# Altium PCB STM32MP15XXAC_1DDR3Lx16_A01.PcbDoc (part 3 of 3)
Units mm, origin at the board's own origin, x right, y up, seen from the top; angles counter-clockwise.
Board outline 89 x 120 mm, 4 copper layers (Top Layer, Signal Layer 1, Signal Layer 2, Bottom Layer), stack 1.571 mm thick; 133 components, 92 nets, 915 pads, 400 vias.
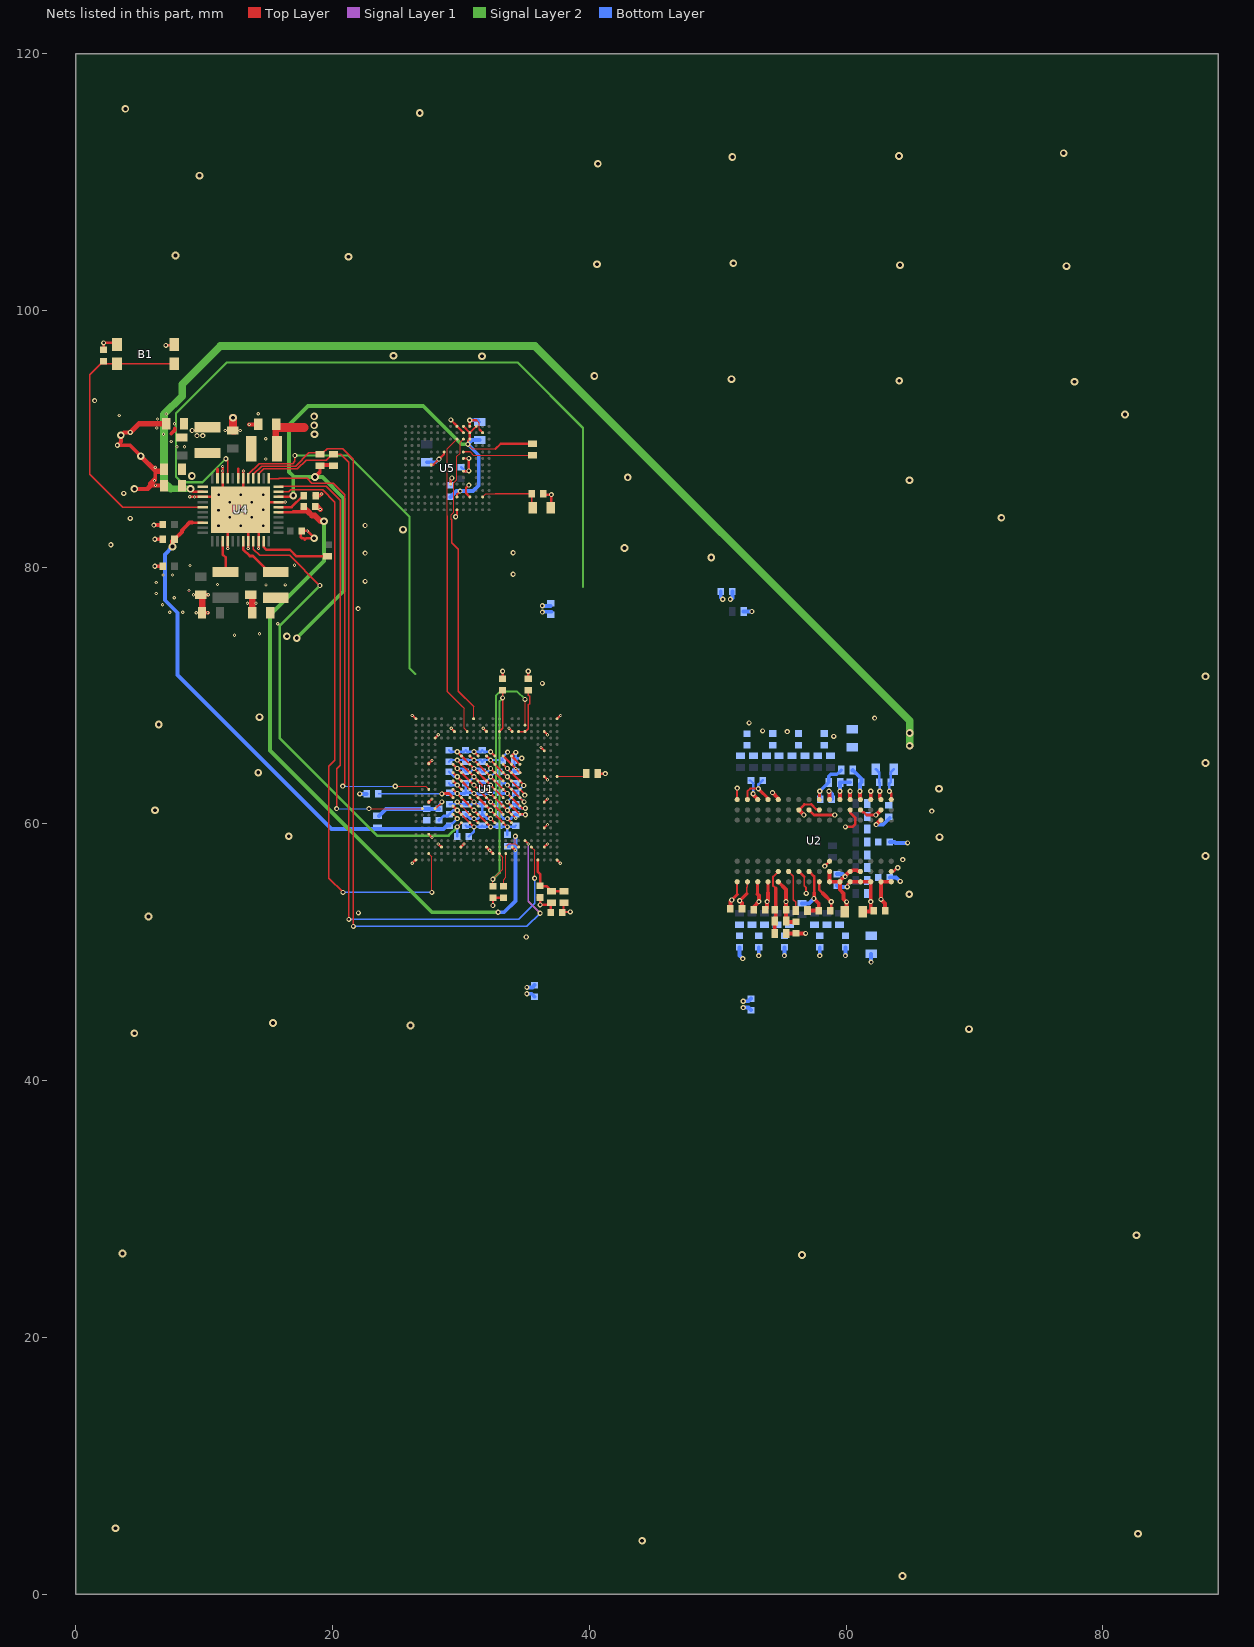
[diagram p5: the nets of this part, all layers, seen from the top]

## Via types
v1: diameter 0.4, hole 0.2, Top Layer to Bottom Layer, tented both sides, 241 vias
v2: diameter 0.6, hole 0.3, Top Layer to Bottom Layer, tented both sides, 81 vias
v3: diameter 0.25, hole 0.1, Top Layer to Signal Layer 1, tented top, 72 vias
v4: diameter 0.25, hole 0.1, Top Layer to Signal Layer 1, tented both sides, 6 vias

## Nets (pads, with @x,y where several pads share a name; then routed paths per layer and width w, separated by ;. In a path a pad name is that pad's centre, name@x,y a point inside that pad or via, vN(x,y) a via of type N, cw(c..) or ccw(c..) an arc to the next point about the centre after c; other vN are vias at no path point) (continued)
GND: B1.1 B1.2 C1.2 C2.2 C3.2 C4.2 C5.2 C6.2 C7.2 C8.2 C9.2 C10.2 C11.2 C12.2 C13.1 C14.1 C15.1 C16.1 C17.2 C18.1 C19.2 C20.2 C21.2 C22.2 C23.2 C24.2 C25.2 C26.2 C29.1 C30.1 C31.1 C32.1 C33.1 C34.1 C35.1 C36.1 C37.1 C38.1 C39.1 C40.1 C41.1 C42.1 C43.2 C44.1 C45.1 C46.1 C47.1 C48.1 C49.1 C50.1 C51.1 C52.1 C53.1 C54.1 C55.1 C56.1 C57.1 C61.1 C66.1 C67.1 C68.1 C69.1 C70.1 C71.1 C72.1 C75.1 C76.1 C77.1 C78.1 C79.1 C80.1 C81.1 C82.1 C83.1 C84.2 C85.2 C86.2 C87.2 C88.1 C89.2 C90.2 C92.1 C94.1 C95.1 C96.1 C97.1 R26.1 R27.2 R28.1 R29.1 R32.1 R42.1 R44.1 U1.1A3 U1.1A5 U1.1A7 U1.1B2 U1.1B4 U1.1B6 U1.1B8 U1.1C1 U1.1C3 U1.1C5 U1.1C7 U1.1C9 U1.1D2 U1.1D4 U1.1D6 U1.1D8 U1.1E1 U1.1E3 U1.1E5 U1.1E7 U1.1E9 U1.1F2 U1.1F4 U1.1F6 U1.1F8 U1.1G1 U1.1G3 U1.1G5 U1.1G7 U1.1G9 U1.1H2 U1.1H4 U1.1H6 U1.1H8 U1.1J3 U1.1J5 U1.1J7 U1.A1 U1.A23 U1.AA5 U1.AA8 U1.AA12 U1.AA16 U1.AA21 U1.AB13 U1.AC1 U1.AC23 U1.C7 U1.C12 U1.C16 U1.C21 U1.D4 U1.F21 U1.H3 U1.K21 U1.P3 U1.P21 U1.V21 U1.W3 U2.A9 U2.B1 U2.B3 U2.B9 U2.D1 U2.D8 U2.E1 U2.E2 U2.E8 U2.F9 U2.G1 U2.G8 U2.G9 U2.J2 U2.J8 U2.M1 U2.M9 U2.P1 U2.P9 U2.T1 U2.T9 U4.6 U4.10 U4.15 U4.26 U4.30 U4.32 U4.41 U4.ep U5.A6 U5.C4 U5.E7 U5.G5 U5.H10 U5.J5 U5.K8 U5.N2 U5.N5 U5.P4 U5.P6 | length 188
  Top Layer w0.09: 31.225,91.45 31.45,91.225 31.45,90.725
  Top Layer w0.12: U2.M1@54.725,61.9 U2.M1@54.725,62 ; v1(58.675,62.55) v1@58.725,62.5
  Top Layer w0.15: 51.525,54.51 U2.T9@51.525,55.55 ; U2.T1@51.525,61.9 v1(51.525,62.8) ; v1@52.765,62.31 v1(52.765,62.36)
  Top Layer w0.175: v3(26.225,56.95) 26.475,57.2 U1.AC1@26.5,57.2 ; v3(26.225,68.45) 26.25,68.45 U1.A1@26.5,68.2 ; U1.W3@27.5,59.2 v3(27.75,58.95) ; U1.P3@27.5,61.7 v3(27.75,61.95) ; U5.H10@27.7,87.975 27.85,87.975 v1(28.3,88.425) 28.7,88.825 U5.K8@28.7,88.975 ; U1.D4@28,66.7 v3(28.25,66.95) ; v3(28.25,58.45) U1.AA5@28.5,58.2 ; v1(29.225,91.475) 29.7,91 U5.P6@29.7,90.975 U5.N5@30.2,90.475 ; v3(29.25,67.45) U1.C7@29.5,67.2 ; U1.1G1@29.4,61.4 U1.1J3@30.7,60.1 v1(31.025,59.775) ; U1.1E1@29.4,62.7 U1.1G3@30.7,61.4 U1.1J5@32,60.1 v1(32.325,59.775) ; U1.1C1@29.4,64 U1.1D2@30.05,63.35 U1.1E3@30.7,62.7 U1.1G5@32,61.4 U1.1H6@32.65,60.75 U1.1J7@33.3,60.1 v1(33.625,59.775) ; v1(29.6,83.925) 29.7,84.025 U5.A6@29.7,84.475 ; v1(29.725,64.975) v1(31.025,63.675) U1.1E5@32,62.7 v1(32.325,62.375) U1.1F6@32.65,62.05 U1.1G7@33.3,61.4 U1.1H8@33.95,60.75 33.975,60.75 v3(34.275,60.45) ; U5.G5@30.2,87.475 30.601,87.475 v1(30.625,87.5) v1(30.625,88.475) U5.J5@30.2,88.475 ; v1(30.625,86.4) 30.4,86.175 30.4,85.775 U5.C4@30.7,85.475 ; U1.1A3@30.7,65.3 U1.1B4@31.35,64.65 U1.1C5@32,64 U1.1E7@33.3,62.7 U1.1F8@33.95,62.05 U1.1G9@34.6,61.4 34.775,61.225 v1(35.025,61.225) ; U5.P4@30.7,90.948 U5.P4@30.7,90.975 v1(30.7,91.45) 31.225,91.45 ; 31.45,90.725 U5.N2@31.7,90.475 ; v3(31.75,67.45) U1.C12@32,67.2 ; U1.1A5@32,65.3 v1(32.325,64.975) U1.1C7@33.3,64 U1.1E9@34.6,62.7 34.975,62.325 v1(34.975,62.25) ; v1(32.5,53.65) C67.1@32.5,54.25 C69.1@33.325,54.25 ; U1.1A7@33.3,65.3 U1.1B8@33.95,64.65 U1.1C9@34.6,64 ; v3(33.75,67.45) U1.C16@34,67.2 ; U1.1C9@34.6,63.975 U1.1C9@34.6,64 ; U1.1C9@34.625,64 U1.1C9@34.6,64 ; v3(36.25,65.95) U1.F21@36.5,65.7 ; C82.1@36.425,85.725 36.5,85.65 v1(37.05,85.65) 37.05,84.675 C83.1@37,84.625 ; U1.AA21@36.5,58.2 v3(36.75,58.45) ; U1.V21@36.5,59.7 v3(36.75,59.95) ; U1.P21@36.5,61.7 v3(36.75,61.95) ; U1.K21@36.5,63.7 v3(36.75,63.45) ; U1.C21@36.5,67.2 v3(36.75,66.95) ; U1.AC23@37.5,57.2 v3(37.75,56.95) ; U1.A23@37.5,68.2 37.75,68.45 v3(37.775,68.45)
  Top Layer w0.2: C44.1@2.175,96.95 v1(2.175,97.475) 3.1,97.475 B1.1@3.225,97.35 ; v1(7.025,97.275) 7.6,97.275 B1.2@7.675,97.35 ; v4(8.882,85.482) 9.243,85.482 v4(9.25,85.475) U4.15@9.9,85.475 10.875,85.475 U4.ep@10.9,85.45 ; v3@11.45,87.825 v3(11.45,87.5) U4.10@11.45,86.925 11.45,85.875 v1(12.85,84.475) ; v3(11.85,81.45) U4.26@11.85,82.025 11.85,83.475 v1(12.85,84.475) ; v2(12.255,91.64) v2@12.381,91.514 ; v3@13.05,87.5 U4.6@13.05,86.925 U4.ep@13.05,84.675 ; v3@13.45,81.425 v3(13.45,81.45) U4.30@13.45,82.025 U4.ep@13.45,83.875 ; v3(14.25,81.45) U4.32@14.25,82.025 14.25,83.075 U4.ep@13.45,83.875 ; v3(16.325,85.075) U4.41@15.8,85.075 13.45,85.075 U4.ep@13.05,84.675 ; C51.1@17.537,82.762 17.537,82.338 17.625,82.25 17.757,82.25 17.857,82.15 17.957,82.25 v2(18.575,82.25) ; C51.1@17.6,82.825 v3(18.05,82.825) v2@18.6,82.275 ; U1.H3@27.5,64.7 v3(27.75,64.95) ; U5.E7@29.2,86.475 29.2,86.825 v1@29.325,86.95 ; U1.AA8@30,58.2 v3(30.25,58.45) ; U1.AA12@32,58.2 v3(32.25,57.95) U1.AB13@32.5,57.7 ; C66.1@33.25,71.3 v1(33.25,71.9) ; U1.AA16@34,58.2 v3(34.25,57.95) ; C68.1@35.25,71.3 v1(35.25,71.9) ; C72.1@36,54.275 36.175,54.1 v1(36.175,53.7) 37,53.7 C88.1@37,53.1 C88.1@37,53.05 ; R27.2@40.675,63.925 v1(41.25,63.925) ; 53.105,54.53 53.105,55.48 U2.P9@53.125,55.5 ; R44.1@55.35,52.45 R44.1@55.425,52.375 ; U2.J8@57.105,56.343 57.525,55.923 57.525,54.625 ; U2.J2@57.125,61.1 57.525,60.7 v1(59.125,60.7) ; v1(59.95,59.775) 60.5,59.775 60.725,60 60.725,60.48 60.325,60.88 U2.E2@60.325,61.15 ; U2.D1@61.085,61.94 U2.D1@61.125,61.9 ; v1(61.085,62.55) v1@61.125,62.51 ; U2.B1@62.625,62 U2.B1@62.725,61.9 ; v1(12.85,84.475) U4.ep@13.05,84.675 ; v1(12.85,84.475) U4.ep@13.45,83.875
  Top Layer w0.25: v1@51.095,54.08 51.525,54.51
  Top Layer w0.3: v1(4.25,90.5) 3.75,90.5 v2(3.525,90.275) 3.525,89.775 v1(3.25,89.5) 4.225,89.5 v2(5.075,88.65) ; v2(4.575,86.1) 5.65,86.1 5.675,86.125 ; v1(6.1,83.275) 6.75,83.275 C41.1@6.8,83.325 C41.1@6.775,83.35 ; v3(6.144,86.744) 5.925,86.525 5.925,86.5 ; v1(6.175,80.075) C32.1@6.8,80.075 ; v1(6.175,82.175) C49.1@6.8,82.175 ; v3(6.2,87.775) 6.2,87.525 6.2,86.95 ; C46.1@6.85,86.375 v3(6.214,86.375) 5.925,86.375 ; 7.45,90.4 7.725,90.675 7.725,90.8 ; C39.1@9.75,77.85 v3(10.325,77.85) ; C40.1@9.85,76.45 v3(10.3,76.45) ; C33.1@12.255,90.701 12.25,90.696 12.227,90.673 C33.1@12.25,90.65 C33.1@12.4,90.5 ; v3@13.5,91.125 v3(13.525,91.125) 13.95,91.125 C34.1@14.2,90.875 ; C43.2@18.6,85.575 C43.2@18.65,85.525 ; C43.2@18.684,85.562 19.012,85.562 v3(19.15,85.7) ; C21.2@51,53.4 51,53.975 v1(51.105,54.08) ; v1@52.765,62.31 U2.P1@53.15,61.925 ; C20.2@52.825,53.325 52.825,53.56 v1(53.215,53.95) 53.215,54.42 53.105,54.53 ; v1(54.275,62.45) U2.M1@54.725,62 ; U2.M9@54.725,55.5 55.325,54.9 v1(55.325,53.95) 55.325,52.475 R44.1@55.35,52.45 ; R44.1@55.425,52.375 C90.2@56.1,52.375 ; R29.1@57,53.25 C19.2@57.875,53.25 57.875,53.81 v1@57.525,54.16 ; v1(57.5,54.2) 57.5,54.185 v1@57.525,54.16 ; 57.525,54.625 v1@57.525,54.16 ; U2.G9@58.725,55.5 U2.G9@58.725,55.55 ; U2.G8@58.725,56.3 U2.G9@58.725,55.55 ; U2.G1@58.725,61.9 v1@58.725,62.5 ; U2.F9@59.505,55.543 60.305,56.343 60.438,56.343 60.489,56.393 60.861,56.393 60.912,56.343 U2.D8@61.053,56.343 ; U2.F9@59.525,55.55 U2.F9@59.525,55.5 ; C15.1@59.9,53.175 60.045,53.32 v1(60.045,53.93) 59.805,54.17 59.805,54.595 59.525,54.875 U2.F9@59.525,55.5 ; U2.E1@60.325,61.9 v1(60.325,62.55) ; U2.D1@61.085,61.94 v1(61.085,62.55) ; v1(62.35,59.95) 62.7,60.3 U2.B3@62.725,60.3 ; U2.B1@62.625,62 v1(62.625,62.55) ; C17.2@63.05,53.25 63.05,53.8 v1(62.725,54.125) U2.B9@62.725,55.5 U2.A9@63.525,55.5 ; 5.675,86.125 5.675,86.25 5.863,86.438 ; 5.675,86.125 5.925,86.375 ; 5.863,86.438 5.925,86.5 ; 5.863,86.438 5.925,86.375 ; 5.863,86.438 5.775,86.525 6.2,86.95 ; 5.925,86.375 5.925,86.5 ; 5.925,86.5 6.2,86.775 6.2,86.95 ; U2.G9@58.725,55.55 58.775,55.5 U2.F9@59.525,55.5
  Top Layer w0.4: v1(4.25,90.5) 4.925,91.175 C29.1@7.05,91.175 ; v2(5.075,88.65) 6.2,87.525 6.25,87.475 C42.1@6.6,87.475 ; C52.1@18.751,84.801 v3(19.053,84.5)
  Top Layer w0.5: C18.1@8.125,90.1 C18.1@8.25,90.1 ; C39.1@9.75,77.85 9.85,77.75 C40.1@9.85,76.45 ; C31.1@13.625,77.85 13.625,77.75 13.75,77.625 C38.1@13.75,76.45
  Top Layer w0.6: C33.1@12.25,90.65 12.25,90.696 12.25,91.635 v2(12.255,91.64)
  Bottom Layer w0.15: C22.2@52.5,63.4 52.55,63.4 C22.2@52.765,63.185 ; v1(58.675,62.55) v1@58.75,62.625
  Bottom Layer w0.175: C75.1@29.075,64.075 29.475,63.675 v1(29.725,63.675) 30.225,63.175 C37.1@30.375,63.175 30.525,63.175 v1(31.025,63.675) 31.525,63.175 C36.1@31.675,63.175 31.825,63.175 v1(32.325,63.675) 32.725,64.075 C45.1@32.975,64.075 33.225,64.075 v1(33.625,63.675) 34.125,63.175 C57.1@34.275,63.175 ; C35.1@29.075,64.85 29.2,64.975 v1(29.725,64.975) v1(31.025,64.975) 31.55,64.975 C76.1@31.675,64.85 31.8,64.975 v1(32.325,64.975) C53.1@33.25,64.975 ; C96.1@30.375,59.875 C96.1@30.475,59.775 ; C47.1@30.625,59.025 31.025,59.425 v1(31.025,59.775) ; C81.1@31.325,91.45 C81.1@31.475,91.3 ; C95.1@31.575,59.775 C95.1@31.675,59.875 C95.1@31.775,59.775 ; C55.1@32.875,59.775 C55.1@32.975,59.875 C55.1@33.075,59.775 ; C53.1@33.275,64.95 C53.1@33.25,64.975 ; v1(33.65,65.6) 33.25,65.2 C53.1@33.25,64.975 ; C54.1@34.175,59.775 C54.1@34.275,59.875
  Bottom Layer w0.2: C97.1@28.3,60.35 C97.1@28.3,60.275 28.65,60.625 28.975,60.625 29.425,61.075 v1(29.725,61.075) ; C94.1@29.125,62.425 29.175,62.375 v1(29.725,62.375) 30.325,62.375 C48.1@30.375,62.425 ; C80.1@29.2,86.375 29.2,86.825 v1@29.325,86.95 ; C78.1@30.025,87.8 30.35,87.475 30.6,87.475 v1(30.625,87.5) ; C37.1@30.375,63.175 C48.1@30.375,62.425 ; C96.1@30.475,59.775 v1(31.025,59.775) C95.1@31.575,59.775 ; C92.1@31.675,62.425 C92.1@31.725,62.375 ; C95.1@31.775,59.775 v1(32.325,59.775) C55.1@32.875,59.775 ; C55.1@33.075,59.775 v1(33.625,59.775) ; C71.1@33.625,59.175 v1(33.625,59.775) ; v1(33.625,61.075) 34.075,61.525 C56.1@34.275,61.525 34.575,61.225 v1(35.025,61.225) ; v1(33.625,62.375) 33.025,62.375 C77.1@32.975,62.425 32.375,62.425 v1(32.325,62.375) C92.1@31.725,62.375 ; C54.1@34.175,59.775 v1(33.625,59.775) ; v1(52.765,62.36) C22.2@52.765,63.185 ; C16.1@62.325,64.275 62.575,64.025 C24.2@62.575,63.25 62.625,63.2 v1(62.625,62.55) ; C48.1@30.375,62.425 30.975,62.425 v1(31.025,62.375) C92.1@31.725,62.375
  Bottom Layer w0.3: v1(22.125,62.35) C61.1@22.675,62.35 ; C79.1@27.35,88.175 28.05,88.175 v1(28.3,88.425) ; v1(30.7,91.45) C81.1@31.325,91.45 ; v1(35.15,47.275) 35.575,47.275 C87.2@35.75,47.45 ; v1@36.325,76.975 C84.2@36.975,76.975 ; v1(51,77.5) 51.036,77.5 51.15,77.614 C85.2@51.15,78.1 ; C2.2@51.705,50.395 51.705,49.77 v1(51.955,49.52) ; v1(52,45.7) 52.4,45.7 C86.2@52.6,45.5 ; R28.1@52.025,76.55 v1(52.675,76.55) ; v1(53.205,49.745) C3.2@53.205,50.395 ; v1(55.205,49.745) C4.2@55.205,50.395 ; R26.1@56.58,53.82 57.12,53.82 v1(57.5,54.2) ; v1(57.955,49.745) C1.2@57.955,50.395 ; v1(58.675,62.55) 58.9,62.325 C25.2@58.9,61.925 ; C23.2@59.3,56.1 59.725,56.1 v1(59.925,55.9) ; v1(59.955,49.745) C5.2@59.955,50.395 ; R42.1@60.5,64.175 R42.1@60.525,64.2 61.2,63.525 C89.2@61.2,63.25 61.085,63.135 v1(61.085,62.55) ; v1(61.955,49.245) C13.1@61.955,49.895 ; v1@62.325,59.9 62.385,59.96 62.9,59.96 C8.2@63.405,60.465 ; C6.2@63.405,55.845 63.905,55.845 v1@64.105,55.645 ; C7.2@63.405,58.595 63.78,58.595 63.85,58.525 v1(64.8,58.525)
  other v1: 35.1,51.2 22.025,53.075 64.225,55.525 64.425,57.225 66.675,61 31.025,61.075 32.325,61.075 59.05,66.825 55.425,67.2 53.5,67.25 52.45,67.875 62.225,68.25 36.35,70.95 22,76.775 36.35,77 22.55,78.9 34.075,79.45 22.55,81.1 34.075,81.125 2.75,81.75 11.125,83.225 12.875,83.225 14.6,83.225 22.55,83.25 4.25,83.801 12,83.875 13.725,83.875 11.125,84.45 14.6,84.475 12,85.075 13.725,85.075 11.15,85.65 12.875,85.65 14.6,85.65 3.75,85.75 29.3,86.95 1.475,92.975
  other v2: 64.4,1.425 44.125,4.175 82.75,4.725 3.1,5.15 56.575,26.425 3.65,26.55 82.625,27.975 4.575,43.7 69.575,44.025 26.075,44.3 15.375,44.5 5.675,52.8 64.925,54.525 88,57.5 67.275,58.975 16.6,59.05 6.175,61.075 67.25,62.75 14.225,64 88,64.75 6.475,67.75 14.325,68.325 88,71.5 49.5,80.75 42.75,81.5 25.5,82.925 72.1,83.85 64.95,86.775 43,87 81.725,91.9 77.8,94.45 64.15,94.525 51.075,94.65 40.4,94.9 31.65,96.425 24.75,96.475 77.175,103.45 64.2,103.525 40.6,103.6 51.225,103.675 21.25,104.175 7.775,104.275 9.65,110.5 40.675,111.425 51.15,111.95 64.125,112.025 76.95,112.25 26.8,115.375 3.875,115.7
  other v3: 34.275,64.325 12.375,74.7 14.325,74.825 15.75,75.6 9.4,76.45 6.775,77.075 13.375,77.2 14.05,77.2 7.675,77.625 9.175,77.85 8.825,78.175 14.825,78.625 16.325,78.625 11.05,78.65 6.8,79.4 7.55,79.4 8.911,80.125 17.05,80.15 13.075,87.5 11.45,87.85 14.8,88.425 7.9,89.375 8.475,89.375 7.45,89.8 14.8,90 6.85,90.35 11.65,90.65 12.825,90.65 6.325,90.85 7.7,91.175 6.375,91.55 3.4,91.825 7.05,91.925 14.225,91.95
  other v4: 7.325,76.5 8.35,76.5 6.275,77.95 6.275,78.8
I2C4_SCL: R37.2 U1.Y18 U4.4 | length 66.8
  Top Layer w0.1: U4.4@13.85,86.925 13.85,87.237 14.488,87.875 17.125,87.875 18.15,88.9 19.025,88.9 19.26,88.9 19.6,89.24 20.81,89.24 21.638,88.413 v1(21.638,52.025) ; U1.Y18@35,58.7 v3(35.25,58.45)
  Signal Layer 1 w0.1: v3(35.25,58.45) 35.25,53.975 v1(36.175,53.05)
  Bottom Layer w0.1: v1(21.638,52.025) 35.15,52.025 v1(36.175,53.05)
I2C4_SDA: R38.2 U1.AA19 U4.3 | length 63.3
  Top Layer w0.09: U1.AA19@35.5,58.2 35.75,57.95 v1(35.75,55.775)
  Top Layer w0.1: U4.3@14.25,86.925 14.25,87.267 14.658,87.675 17.275,87.675 17.95,88.35 19.525,88.35 20.012,88.838 R38.2@19.975,88.875 ; R38.2@20.074,88.813 20.637,88.813 21.288,88.162 v1(21.288,52.575)
  Bottom Layer w0.1: v1(21.288,52.575) 34.5,52.575 35.75,53.825 v1(35.75,55.775)
NetB1_3: B1.3 B1.4 C44.2 U4.17 | length 24.5
  Top Layer w0.1: B1.4@7.675,95.85 B1.3@3.225,95.85 2.175,95.85 1.95,95.85 1.1,95 1.1,87.25 3.675,84.675 U4.17@9.9,84.675
NetC25_1: C25.1 R33.1 R42.2 U2.H1 | length 3.9
  Top Layer w0.25: U2.H1@57.925,61.9 57.925,62.52 v1(57.955,62.55)
  Bottom Layer w0.25: C25.1@58,61.925 57.955,61.97 v1(57.955,62.55) 57.955,62.555 R33.1@58.65,63.25 58.65,63.725 58.8,63.875 59.3,63.875 R42.2@59.625,64.2
NetC26_1: C26.1 R34.1 R44.2 U2.M8 | length 5.1
  Top Layer w0.15: 54.525,54.975 54.325,55.175 54.325,55.9 U2.M8@54.725,56.3
  Top Layer w0.3: R34.1@54.45,51.475 R44.2@54.45,52.45 54.525,52.525 54.525,53.325 54.525,54.975
NetC43_1: C43.1 U4.40 | length 2.2
  Top Layer w0.2: U4.40@15.8,84.675 16.828,84.675 C43.1@17.689,85.536
NetC61_2: C61.2 U1.1F1 | length 6
  Top Layer w0.2: v1@28.55,62.375 29.075,62.375 U1.1F1@29.4,62.05
  Top Layer w0.3: v1@28.475,62.35 v1(28.525,62.35) v1@28.55,62.375
  Bottom Layer w0.1: C61.2@23.575,62.35 v1(28.525,62.35)
NetC68_2: C68.2 U1.C17 U1.C18 | length 3.9
  Top Layer w0.1: U1.C17@34.5,67.2 U1.C18@35,67.2 35.025,67.2 35.25,67.425 35.25,69.275 35.35,69.375 35.35,69.945 35.25,70.045 C68.2@35.25,70.4
NetC69_2: C69.2 U1.AB15 | length 2.6
  Top Layer w0.09: C69.2@33.325,55.15 33.325,55.675 33.5,55.85 U1.AB15@33.5,57.7
NetC72_2: C72.2 R31.1 R32.2 U1.AC20 | length 4.1
  Top Layer w0.2: U1.AC20@36,57.2 36,56.275 36.2,56.075 36.2,55.175 36.2,55.15 36.7,55.15 R32.2@37.075,54.775 R31.1@38.05,54.775
NetC82_2: C82.2 C83.2 U5.C2 | length 5.1
  Top Layer w0.09: U5.C2@31.7,85.475 31.95,85.725 32.7,85.725
  Top Layer w0.1: 32.7,85.725 C82.2@35.525,85.725 35.525,84.7 C83.2@35.6,84.625
NetL1_1: L1.1 U4.7 | length 0.7
  Top Layer w0.2: U4.7@12.65,86.925 12.65,87.672
NetL2_1: L2.1 U4.11 | length 0.7
  Top Layer w0.2: U4.11@11.05,86.925 11.05,87.65
NetL3_1: L3.1 U4.29 | length 3.9
  Top Layer w0.2: U4.29@13.05,82.025 13.05,81.39 13.565,80.875 13.8,80.875 15.05,79.625 L3.1@15.575,79.625
NetL4_1: L4.1 U4.25 | length 2.4
  Top Layer w0.2: U4.25@11.45,82.025 11.45,81 11.675,80.775 L4.1@11.675,79.725
NetR27_1: R27.1 U1.K23 | length 2.3
  Top Layer w0.09: U1.K23@37.5,63.7 39.75,63.7 R27.1@39.775,63.725
NetR29_2: R29.2 U2.L8 | length 3.3
  Top Layer w0.12: U2.L8@55.525,56.3 55.9,55.925 55.9,54.1 56.1,53.9 R29.2@56.1,53.25 R29.2@56.1,53.225
NetR40_1: R40.1 U5.K5 | length 5.5
  Top Layer w0.09: 30.725,88.975 30.975,88.725 R40.1@35.575,88.725
  Top Layer w0.1: U5.K5@30.2,88.975 30.725,88.975
NetR43_1: R43.1 U4.33 | length 5.7
  Top Layer w0.2: U4.33@14.65,82.025 14.65,81.561 14.836,81.375 16.675,81.375 17.2,80.85 R43.1@19.625,80.85
NRST: U1.M3 U4.1 | length 36
  Top Layer w0.09: v1(24.89,62.94) 27.26,62.94 U1.M3@27.5,62.7
  Top Layer w0.1: U4.1@15.05,86.875 15.82,86.875 15.87,86.925 18.025,86.925 18.4,86.55 20.075,86.55 20.975,85.65 20.975,63.125 v1(20.8,62.95)
  Bottom Layer w0.09: v1(20.8,62.95) 24.88,62.95 v1(24.89,62.94)
PA0_WKUP: U1.AB3 U4.43 | length 46
  Top Layer w0.09: U1.AB3@27.5,57.7 27.75,57.45 v1(27.75,54.675)
  Top Layer w0.1: U4.43@15.8,85.875 16.614,85.875 16.764,86.025 19.25,86.025 20.2,85.075 20.2,64.975 19.725,64.5 19.725,55.775 v1(20.825,54.675)
  Bottom Layer w0.1: v1@20.8,54.675 v1(20.825,54.675) v1(27.75,54.675)
PWR_ON: U1.R2 U4.44 | length 36.1
  Top Layer w0.09: v1@22.825,61.2 v1(22.85,61.2) U1.R2@27,61.2
  Top Layer w0.1: U4.44@15.85,86.225 15.925,86.3 19.525,86.3 20.6,85.225 20.6,64.575 20.325,64.3 v1(20.325,61.2)
  Bottom Layer w0.09: v1(20.325,61.2) v1(22.85,61.2)
SDMMC2_CK: U1.C9 U5.M6 | length 23.7
  Top Layer w0.09: 28.95,84 28.95,89.225 U5.M6@29.7,89.975 ; 30.137,69.138 30.25,69.025 30.25,67.45 U1.C9@30.5,67.2
  Top Layer w0.13: 28.95,84 28.95,70.325 30.137,69.138
SDMMC2_CMD: U1.A10 U5.M5 | length 22.9
  Top Layer w0.09: 29.255,83.745 29.255,84.068 29.46,84.273 29.46,86.574 29.7,86.814 29.7,88.636 29.95,88.886 29.95,89.725 U5.M5@30.2,89.975 ; U1.A10@31,68.2 31,69.15
  Top Layer w0.13: 29.255,83.745 29.3,83.7 29.3,81.9 29.8,81.4 29.8,70.35 31,69.15
VDD: C38.2 C47.2 C48.2 C80.2 C81.2 C92.2 C94.2 C95.2 C96.2 L3.2 R37.1 R38.1 R40.2 U1.1F3 U1.1G2 U1.1G4 U1.1H3 U1.1H5 U1.1J2 U1.1J4 U1.1J6 U1.B18 U4.31 U4.42 U5.C6 U5.M4 U5.N4 U5.P3 U5.P5 | length 120.2
  Top Layer w0.09: v1(30.55,89.575) 30.9,89.225 32.7,89.225 ; U1.B18@35,67.7 v1(35,69.7) v1@35,69.8
  Top Layer w0.1: U4.31@13.85,82.025 13.85,81.4 14.325,80.925 16.675,80.925 v1(19.025,78.575)
  Top Layer w0.12: v1(29.725,59.775) U1.1J2@30.05,60.1 ; v1(29.725,61.725) U1.1G2@30.05,61.4 U1.1H3@30.7,60.75 v1(31.025,60.425) U1.1J4@31.35,60.1 ; U1.1F3@30.7,62.05 v1(31.025,61.725) U1.1G4@31.35,61.4 ; U1.1H5@32,60.75 v1(32.325,60.425) U1.1J6@32.65,60.1
  Top Layer w0.175: U5.C6@29.7,85.475 29.7,85.675 v1(29.95,85.925) ; U5.P5@30.2,90.975 U5.N4@30.7,90.475 ; v1(30.55,89.575) 30.55,89.825 U5.M4@30.7,89.975 U5.N4@30.7,90.475 ; U5.P3@31.2,90.975 U5.N4@30.7,90.475 ; 32.7,89.225 33.1,89.625 R40.2@35.575,89.625
  Top Layer w0.2: U4.42@15.8,85.475 v2@16.85,85.475 ; v2@16.85,85.475 v2(16.95,85.575) ; v2@16.85,85.475 v2(16.95,85.575) ; v2(16.95,85.575) 16.95,85.579 v2(16.95,85.575) v2(16.95,85.575)
  Top Layer w0.25: 19,87.375 19.025,87.4 R37.1@19.025,87.9
  Top Layer w0.3: v2@18.65,87.15 v2(18.65,87.025) 19,87.375 ; R37.1@19.325,87.95 20.074,87.95 R38.1@20.175,87.95
  Signal Layer 2 w0.15: 32.6,60.675 32.725,60.8 32.725,69.975 33.075,70.325 34.375,70.325 v1(35,69.7)
  Signal Layer 2 w0.2: 16.95,87.1 17.025,87.025 ; v1(19.025,78.575) 15.9,75.45 15.9,66.675 23.475,59.1 29.05,59.1 v1(29.725,59.775)
  Signal Layer 2 w0.3: v2(16.95,85.575) 16.95,87.1 16.625,87.425 16.625,91.075 18.1,92.55 27.075,92.55 30.05,89.575 v1(30.55,89.575) ; 17.025,87.025 v2(18.65,87.025) 19.225,87.025 20.875,85.375 20.875,78.125 v2(17.225,74.475)
  Bottom Layer w0.09: C48.2@30.375,61.525 C48.2@30.4,61.5
  Bottom Layer w0.175: C47.2@29.725,59.025 v1(29.725,59.775)
  Bottom Layer w0.2: C94.2@29.125,61.525 29.525,61.525 v1(29.725,61.725) 29.925,61.525 C48.2@30.375,61.525 ; C96.2@30.375,60.775 30.725,60.425 v1(31.025,60.425) 31.325,60.425 C95.2@31.675,60.775 ; C48.2@30.4,61.5 30.8,61.5 v1(31.025,61.725) 31.225,61.525 C92.2@31.675,61.525 C95.2@31.675,60.775 ; v1(32.325,60.425) 32.025,60.425 C95.2@31.675,60.775
  Bottom Layer w0.3: C80.2@29.2,85.475 29.65,85.925 v1(29.95,85.925) 30.95,85.925 31.4,86.375 31.4,88.725 v1(30.55,89.575) 30.875,89.9 C81.2@31.475,89.9
  other v2: 16.45,74.625
VDD_CORE: C30.2 C34.2 C35.2 C36.2 C37.2 C75.2 C76.2 C77.2 L1.2 U1.1A2 U1.1A4 U1.1A6 U1.1B1 U1.1B3 U1.1B5 U1.1C2 U1.1C4 U1.1C6 U1.1D1 U1.1D3 U1.1D5 U1.1D7 U1.1E2 U1.1E4 U1.1E6 U1.1F5 U1.1F7 U1.1G6 U1.1H7 U4.5 | length 54.1
  Top Layer w0.1: U4.5@13.45,86.925 13.45,87.237 14.288,88.075 16.9,88.075 17.075,88.25 v1(17.075,88.7)
  Top Layer w0.175: U1.1D1@29.4,63.35 v1(29.725,63.025) U1.1E2@30.05,62.7 ; U1.1B1@29.4,64.65 v1(29.725,64.325) U1.1C2@30.05,64 U1.1D3@30.7,63.35 v1(31.025,63.025) U1.1E4@31.35,62.7 U1.1F5@32,62.05 v1(32.325,61.725) U1.1G6@32.65,61.4 U1.1H7@33.3,60.75 ; v1(29.725,65.625) U1.1A2@30.05,65.3 U1.1B3@30.7,64.65 v1(31.025,64.325) U1.1C4@31.35,64 U1.1D5@32,63.35 v1(32.325,63.025) U1.1E6@32.65,62.7 U1.1F7@33.3,62.05 ; v1(31.025,65.625) U1.1A4@31.35,65.3 ; U1.1B5@32,64.65 v1(32.325,64.325) U1.1C6@32.65,64 U1.1D7@33.3,63.35 ; v1(32.325,65.625) U1.1A6@32.65,65.3
  Top Layer w0.5: C34.2@15.6,90.875 15.6,89.3 L1.2@15.675,89.225
  Top Layer w0.7: C34.2@15.675,90.875 17.775,90.875
  Signal Layer 2 w0.175: v1(17.075,88.7) 21.225,88.7 26,83.925 26,72.125 26.45,71.675
  Bottom Layer w0.175: C75.2@29.075,63.175 29.225,63.025 v1(29.725,63.025) ; C35.2@29.075,65.75 29.2,65.625 v1(29.725,65.625) 30.25,65.625 C30.2@30.375,65.75 30.5,65.625 v1(31.025,65.625) 31.55,65.625 C76.2@31.675,65.75 31.8,65.625 v1(32.325,65.625) ; v1(29.725,64.325) 30.125,64.325 C37.2@30.375,64.075 30.775,64.075 v1(31.025,64.325) 31.425,64.325 C36.2@31.675,64.075 32.075,64.075 v1(32.325,64.325)
  Bottom Layer w0.2: v1(32.325,61.725) 32.525,61.525 C77.2@32.975,61.525
  other v2: 18.6,90.35 18.575,91.05 18.575,91.75
VDD_DDR: C15.2 C16.2 C17.1 C19.1 C20.1 C21.1 C22.1 C23.1 C24.1 C29.2 C42.2 C45.2 C53.2 C54.2 C55.2 C56.2 C57.2 C84.1 C85.1 C86.1 C87.1 C88.2 C89.1 C90.1 L2.2 R31.2 R33.2 R34.2 U1.1A8 U1.1B7 U1.1B9 U1.1C8 U1.1D9 U1.1E8 U1.1F9 U1.1G8 U1.1H9 U1.1J8 U2.A1 U2.A8 U2.B2 U2.C1 U2.C9 U2.D2 U2.D9 U2.E9 U2.F1 U2.G7 U2.H2 U2.H9 U2.K2 U2.K8 U2.N1 U2.N9 U2.R1 U2.R9 U4.9 U4.13 | length 112.4
  Top Layer w0.1: v1(11.7,88.45) 11.85,88.3 U4.9@11.85,86.925
  Top Layer w0.12: 52.265,54.57 52.265,55.049 52.325,55.109 U2.R9@52.325,55.55 ; U2.C1@61.88,61.889 U2.C1@61.905,61.914
  Top Layer w0.15: U2.R1@52.325,61.9 52.325,62.55 52.525,62.75 v1(53.175,62.75) v1@53.255,62.67 ; 56.75,55.875 56.75,55.2 56.9,55.05 v1(56.9,54.6) ; 56.75,61.525 57.3,61.525
  Top Layer w0.175: U1.1B7@33.3,64.65 v1(33.625,64.325) U1.1C8@33.95,64 U1.1D9@34.6,63.35 34.9,63.05 v1(34.9,63) ; v1(33.625,60.425) U1.1J8@33.95,60.1 ; v1(33.625,61.725) U1.1G8@33.95,61.4 U1.1H9@34.6,60.75 35,60.75 v1(35.025,60.725) ; v1(33.625,63.025) U1.1E8@33.95,62.7 U1.1F9@34.6,62.05 v1(34.925,61.725) ; v1(34.275,65.575) 34.225,65.575 U1.1A8@33.95,65.3 U1.1B9@34.6,64.65 U1.1B9@34.6,64.625 ; C88.2@37.9,53.05 C88.2@38,53.15 ; R31.2@38.05,53.875 38,53.825 C88.2@38,53.15 ; v1(38.525,53.15) C88.2@38,53.15
  Top Layer w0.2: C20.1@53.725,53.325 C20.1@53.855,53.455 ; 53.925,54.645 U2.N9@53.925,55.5 ; U2.K8@56.325,56.35 U2.K8@56.325,56.3 56.75,55.875 ; U2.K2@56.325,61.1 56.75,61.525 ; 57.3,61.525 57.675,61.15 U2.H2@57.925,61.15 ; U2.H9@57.925,55.5 57.925,54.87 58.22,54.575 ; U2.H9@57.925,55.55 U2.H9@57.955,55.55 ; v1(58.35,56.725) U2.G7@58.725,57.1 ; C19.1@58.775,53.25 58.855,53.33 v1(58.855,53.94) ; v1(60.1,55.1) 60.1,55.275 U2.E9@60.325,55.5 ; U2.E9@60.325,55.55 U2.E9@60.325,55.593 ; U2.D2@61.105,61.114 61.133,61.114 U2.D2@61.105,61.143 ; U2.D2@61.125,61.1 61.305,60.92 61.382,60.92 61.602,60.7 v1(62.325,60.7) ; U2.B2@62.705,61.138 U2.B2@62.705,61.143 ; v1(63.385,62.55) 63.525,62.41 U2.A1@63.525,61.9 ; U2.A8@63.525,56.3 63.685,56.3 63.985,56.6 63.995,56.59 v1(64.035,56.59)
  Top Layer w0.25: v1(51.715,54.02) 52.265,54.57 ; v1@53.255,62.67 53.925,62 U2.N1@53.925,61.9
  Top Layer w0.3: v1(51.715,54.02) 51.9,53.835 C21.1@51.9,53.4 ; C20.1@53.855,53.455 v1(53.855,53.95) 53.925,54.02 53.925,54.645 ; R34.2@55.35,51.475 C90.1@56.1,51.475 v1(56.85,51.475) ; U2.K2@56.325,61.1 v1(56.725,60.7) ; 58.22,54.575 v1(58.855,53.94) ; U2.F1@59.525,61.9 v1@59.525,62.51 ; U2.E9@60.325,55.5 U2.D9@61.125,55.5 U2.C9@61.925,55.5 v1(61.925,53.95) 61.925,53.225 61.875,53.175 ; C15.2@61.3,53.175 61.875,53.175 ; U2.C1@61.925,61.9 v1@61.925,62.5 ; C17.1@62.15,53.25 62.075,53.175 61.875,53.175 ; v1(62.325,60.7) U2.B2@62.725,61.1
  Signal Layer 2 w0.175: v1(11.7,88.45) 9.875,86.625 8.25,86.625 7.825,87.05 7.825,92 11.775,95.95 31.436,95.95 31.448,95.937 31.852,95.937 31.864,95.95 34.425,95.95 39.525,90.85 39.525,78.475
  Bottom Layer w0.15: v1(59.525,62.55) v1@59.55,62.575 ; R33.2@59.525,63.225 R33.2@59.55,63.25
  Bottom Layer w0.175: C45.2@32.975,63.175 33.475,63.175 v1(33.625,63.025) 33.898,62.752 33.973,62.752 34.275,62.45 C56.2@34.275,62.425 ; v1(33.625,61.725) C56.2@34.275,62.375 ; v1(33.625,64.325) 33.875,64.075 C57.2@34.275,64.075 34.175,64.175 C53.2@34.175,64.95 C53.2@34.275,65.05 ; C54.2@34.275,60.775 C54.2@34.325,60.725 ; v1(34.275,65.575) C53.2@34.275,65.05 ; v1(34.75,65.125) 34.35,65.125 C53.2@34.275,65.05 ; v1(34.9,63) 34.325,62.425 C56.2@34.275,62.425 ; v1(34.925,61.725) C56.2@34.275,62.375 ; C56.2@34.275,62.375 C56.2@34.275,62.425
  Bottom Layer w0.2: C55.2@32.975,60.775 33.325,60.425 v1(33.625,60.425) 33.925,60.425 C54.2@34.275,60.775 ; C54.2@34.325,60.725 v1(35.025,60.725) ; v1(51.715,54.02) v1@51.78,54.02 ; v1(53.175,62.75) 53.175,63.075 C22.1@53.5,63.4 ; v1(63.385,62.55) 63.385,63.16 C24.1@63.475,63.25 63.475,64.025 C16.2@63.725,64.275
  Bottom Layer w0.3: v1(35.15,46.775) 35.525,46.775 C87.1@35.75,46.55 ; v1@36.437,76.53 C84.1@37.087,76.53 ; C85.1@50.25,78.1 50.25,77.65 v1(50.4,77.5) ; v1(52,46.2) 52.4,46.2 C86.1@52.6,46.4 ; C23.1@59.3,55.2 59.4,55.1 v1(60.1,55.1) ; v1(59.525,62.55) R33.2@59.525,63.225 ; R33.2@59.55,63.25 C89.1@60.3,63.25
  other v1: 61.925,62.55 36.35,76.5 9.45,90.25 9.9,90.25 9.075,90.65
  other v2: 9.05,87.1
VDD_USB: C52.2 C71.2 U1.AA15 U1.AA17 U4.39 | length 57.9
  Top Layer w0.09: U1.AA15@33.5,58.2 33.75,58.45 34.25,58.45 ; v1@34.25,59.125 v1(34.25,59.05) 34.25,58.45 ; U1.AA17@34.5,58.2 34.25,58.45
  Top Layer w0.2: U4.39@15.8,84.275 16.85,84.275 ; C52.2@17.625,84.575 C52.2@17.775,84.725 C52.2@17.775,84.66 ; 16.85,84.275 18.075,84.275 18.117,84.317 18.175,84.375 18.059,84.375 17.775,84.375 16.95,84.375 16.85,84.275
  Top Layer w0.45: C52.2@17.775,84.66 17.775,84.659 18.059,84.375 18.117,84.317 18.409,84.025 18.625,84.025 19.075,83.575 v2(19.35,83.575)
  Signal Layer 2 w0.3: v2(19.35,83.575) 19.35,80.475 15.15,76.275 15.15,65.725 27.75,53.125 v1(32.9,53.125)
  Bottom Layer w0.09: 34.225,58.275 34.25,58.25
  Bottom Layer w0.3: v1(32.9,53.125) 33.375,53.125 34.25,54 34.25,58.25 v1(34.25,59.05) ; C71.2@33.625,58.275 34.225,58.275
VDDA: C49.2 C70.2 R41.1 U1.1H1 U4.20 | length 41.4
  Top Layer w0.09: U1.1H1@29.4,60.75 v1(29.725,60.425)
  Top Layer w0.2: 9.075,83.475 U4.20@9.9,83.475
  Top Layer w0.3: C49.2@7.7,82.175 8.275,82.75 8.275,82.873 8.55,83.148 8.55,83.155 8.87,83.475 9.075,83.475
  Top Layer w0.4: v2(7.55,81.6) 7.55,82.025 C49.2@7.7,82.175
  Bottom Layer w0.2: C70.2@29.35,60.05 v1(29.725,60.425)
  Bottom Layer w0.3: v2(7.55,81.6) 6.95,81 6.95,77.425 7.925,76.45 7.925,71.6 19.925,59.6 23.5,59.6 28.65,59.6 28.925,59.875 C70.2@29.125,59.875
VDDA_1V8: C66.2 C67.2 U1.AB14 U1.C14 | length 20.7
  Top Layer w0.09: C67.2@32.5,55.15 v1(32.5,55.7) 33.275,56.475 33.275,57.425 U1.AB14@33,57.7
  Top Layer w0.1: U1.C14@33,67.2 33.25,67.45 v1(33.25,69.825) C66.2@33.25,70.4
  Signal Layer 2 w0.1: v1@33.25,69.8 v1(33.25,69.825)
  Signal Layer 2 w0.15: 33.025,56.225 33.025,69.575 v1@33.25,69.8
  Signal Layer 2 w0.2: v1(32.5,55.7) 33.025,56.225
VREF+: C50.2 C97.2 R41.2 U1.R4 | length 6.5
  Top Layer w0.1: U1.R4@28,61.2 28.025,61.2 28.537,61.713 v1@28.575,61.75
  Bottom Layer w0.1: R41.2@23.5,60.625 R41.2@23.625,60.625 ; C97.2@28.3,61.175 28.3,61.5 v1(28.525,61.725)
  Bottom Layer w0.3: R41.2@23.625,60.625 24.175,61.175 C50.2@27.35,61.175 C97.2@28.3,61.175
VTT_DDR: C1.1 C2.1 C3.1 C4.1 C5.1 C6.1 C7.1 C8.1 C9.1 C10.1 C11.1 C12.1 C13.2 C14.2 C46.2 R1.2 R2.2 R3.2 R4.2 R5.2 R6.2 R7.2 R8.2 R9.2 R10.2 R11.2 R12.2 R13.2 R15.2 R16.2 R17.2 R18.2 R19.2 R20.2 R21.2 R22.2 R23.2 R24.2 R25.2 U4.14 | length 83.2
  Top Layer w0.2: 9.175,85.875 U4.14@9.9,85.875
  Signal Layer 2 w0.5: 7.4,86.1 v2(8.95,86.1)
  Signal Layer 2 w0.6: 7.4,86.1 6.875,86.625 6.875,91.9 8.3,93.325 8.3,94.25 11.275,97.225 35.775,97.225 64.955,68.045 v2(64.955,67.095) v2(64.955,66.095)
pads on no net: U1.A2 U1.A3 U1.A4 U1.A5 U1.A7 U1.A8 U1.A14 U1.A16 U1.A17 U1.A19 U1.A20 U1.A21 U1.A22 U1.AA1 U1.AA2 U1.AA3 U1.AA4 U1.AA6 U1.AA7 U1.AA9 U1.AA10 U1.AA11 U1.AA13 U1.AA14 U1.AA18 U1.AA20 U1.AA22 U1.AA23 U1.AB1 U1.AB2 U1.AB4 U1.AB5 U1.AB6 U1.AB7 U1.AB8 U1.AB9 U1.AB10 U1.AB11 U1.AB12 U1.AB16 U1.AB17 U1.AB18 U1.AB19 U1.AB20 U1.AB21 U1.AB22 U1.AB23 U1.AC2 U1.AC3 U1.AC4 U1.AC5 U1.AC7 U1.AC8 U1.AC10 U1.AC11 U1.AC13 U1.AC14 U1.AC16 U1.AC17 U1.AC19 U1.AC21 U1.AC22 U1.B1 U1.B2 U1.B3 U1.B4 U1.B5 U1.B6 U1.B7 U1.B8 U1.B9 U1.B14 U1.B15 U1.B16 U1.B17 U1.B19 U1.B20 U1.B21 U1.B22 U1.B23 U1.C1 U1.C2 U1.C3 U1.C4 U1.C5 U1.C6 U1.C8 U1.C10 U1.C15 U1.C19 U1.C20 U1.C22 U1.C23 U1.D1 U1.D2 U1.D3 U1.D5 U1.D6 U1.D7 U1.D8 U1.D9 U1.D10 U1.D11 U1.D12 U1.D13 U1.D14 U1.D15 U1.D16 U1.D17 U1.D18 U1.D19 U1.D21 U1.D22 U1.D23 U1.E1 U1.E2 U1.E3 U1.E4 U1.E23 U1.F2 U1.F3 U1.F4 U1.G1 U1.G2 U1.G3 U1.G4 U1.H1 U1.H2 U1.H4 U1.J2 U1.J3 U1.J4 U1.K1 U1.K2 U1.K3 U1.K4 U1.K20 U1.L1 U1.L2 U1.L3 U1.L4 U1.L21 U1.M2 U1.M4 U1.N1 U1.N2 U1.N3 U1.N4 U1.P1 U1.P2 U1.P4 U1.P20 U1.R3 U1.T1 U1.T2 U1.T3 U1.T4 U1.U1 U1.U2 U1.U3 U1.U4 U1.V2 U1.V3 U1.V4 U1.W1 U1.W2 U1.W4 U1.Y1 U1.Y2 U1.Y3 U1.Y4 U1.Y5 U1.Y6 U1.Y7 U1.Y8 U1.Y9 U1.Y10 U1.Y11 U1.Y12 U1.Y13 U1.Y14 U1.Y15 U1.Y16 U1.Y17 U1.Y19 U1.Y22 U1.Y23 U2.J1 U2.J9 U2.L1 U2.L9 U2.M7 U4.2 U4.16 U4.18 U4.21 U4.23 U4.34 U4.35 U4.38 U5.A1 U5.A2 U5.A7 U5.A8 U5.A9 U5.A10 U5.A11 U5.A12 U5.A13 U5.A14 U5.B1 U5.B7 U5.B8 U5.B9 U5.B10 U5.B11 U5.B12 U5.B13 U5.B14 U5.C1 U5.C3 U5.C5 U5.C7 U5.C8 U5.C9 U5.C10 U5.C11 U5.C12 U5.C13 U5.C14 U5.D1 U5.D2 U5.D3 U5.D4 U5.D12 U5.D13 U5.D14 U5.E1 U5.E2 U5.E3 U5.E5 U5.E8 U5.E9 U5.E10 U5.E12 U5.E13 U5.E14 U5.F1 U5.F2 U5.F3 U5.F10 U5.F12 U5.F13 U5.F14 U5.G1 U5.G2 U5.G3 U5.G10 U5.G12 U5.G13 U5.G14 U5.H1 U5.H2 U5.H3 U5.H5 U5.H12 U5.H13 U5.H14 U5.J1 U5.J2 U5.J3 U5.J12 U5.J13 U5.J14 U5.K1 U5.K2 U5.K3 U5.K6 U5.K7 U5.K10 U5.K12 U5.K13 U5.K14 U5.L1 U5.L2 U5.L3 U5.L12 U5.L13 U5.L14 U5.M1 U5.M2 U5.M3 U5.M7 U5.M8 U5.M9 U5.M10 U5.M11 U5.M12 U5.M13 U5.M14 U5.N1 U5.N3 U5.N6 U5.N7 U5.N8 U5.N9 U5.N10 U5.N11 U5.N12 U5.N13 U5.N14 U5.P1 U5.P2 U5.P7 U5.P8 U5.P9 U5.P10 U5.P11 U5.P12 U5.P13 U5.P14

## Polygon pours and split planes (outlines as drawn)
VDD_DDR on Signal Layer 2 "VDD_DDR" (solid, remove dead copper, pour order 86): 64.35,50.275 52.3,50.275 52.3,45 33.2,45 33.2,90.475 31.025,92.65 13.15,92.65 10.3,89.8 10.3,87.475 9.625,86.8 8.475,86.8 8.125,87.15 8.125,91.775 11.85,95.5 28.475,95.5 33.825,95.5 39,90.325 39,78.75 51.7,78.75 51.7,66.525 64.35,66.525
GND on Signal Layer 2 "NETR16_2_L04_P-001" (solid, pour order 192): 24.25,58.5 29.25,58.5 29.75,59 32.25,59 32.25,56.5 32,56.25 32,54.25 31.5,53.75 28.25,53.75 24.25,57.75
GND on Signal Layer 2 "NETR16_2_L04_P-001" (solid, pour order 190): 20.25,88 21.25,88 25.5,83.75 25.5,66 25.25,65.75 25,65.75 24.5,66.25 19.5,74.75 22,77.25 22,85.5 20.25,87.25
GND on Signal Layer 2 "NETR16_2_L04_P-001" (solid, pour order 188): 40.5,90.25 40.5,79.5 51.25,79.5 51.5,79.75 41,90.25
VDD_CORE on Signal Layer 2 "VDD_CORE" (solid, remove dead copper, pour order 94): 26.225,84.05 20.775,89.5 18.1,89.5 18.1,92.3 26.475,92.3 29.375,89.4 32.725,86.048 32.725,61.409 31.65,61.409 31.65,62.025 31.156,62.5 26.225,62.5
VDD on Signal Layer 2 "VDD" (solid, remove dead copper, pour order 88): 16.126,74.8 16.126,74.751 16.126,74.625 16.126,71.05 23.625,59.475 32.75,59.475 32.75,60.841 31.114,62.375 25.907,62.375 18.355,75.025 16.274,75.025 16.126,74.9
5V_VIN on Signal Layer 2 "5V_VIN" (solid, remove dead copper, pour order 96): 17.65,85.3 17.65,84.775 19.3,84.775 19.3,79.825 15.4,75.925 2.95,75.925 2.95,94.275 7.9,94.275 7.9,85.225 11.325,85.225 11.325,90.7 16.325,90.7 16.325,85.3
GND on Signal Layer 2 "Top Layer-No Net" (solid, remove dead copper, pour order 194): 52.5,78.5 52.5,67 64,67
GND on Signal Layer 2 "Top Layer-No Net" (solid, remove dead copper, pour order 196): 66.5,49.75 52.75,49.75 52.75,43.5 66.5,43.5
GND on Signal Layer 2 "GND_L03_P186" (solid, remove dead copper, pour order 186): 89,82 89,68 66,68 66,69 36,99 11,99 8,96 2,96 2,75 14,75 14,65 27,52 32,52 32,44 66,44 66,68 89,68 89,44 89,0 0,0 0,120 89,120
GND on Top Layer "GND_L01_P182" (solid, remove dead copper, pour order 182): 37.95,69.775 43.05,69.775 43.925,70.65 61.325,70.65 66.9,65.075 89,65.075 89,120 0,120 0,45.675 0,0 89,0 89,65.075 66.9,65.075 66.9,57.575 64.35,55.025 64.35,52.475 61.925,50.05 45.625,50.05 42.175,53.5 42.175,55.775 40.425,57.525 38.575,57.525 37.275,56.225 37.025,56.475 35.275,56.475 35.25,56.5 35.225,56.475 25.775,56.475 25.5,56.75 25.5,68.5 25.75,68.75 29.25,68.75 29.25,69.25 28.25,70.25 28.25,83.75 25,83.75 25,91.5 25.25,91.75 32.5,91.75 32.75,91.5 32.75,86.5 34.25,85 34.25,72.5 33.75,72 33.75,69 34,68.75 36.925,68.75
5V_VIN on Top Layer "NO TR" (solid, remove dead copper, pour order 180): 12.35,88.125 12.35,88.4 13.025,89.075 13.025,90.125 12.925,90.225 11.675,90.225 11.5,90.05 11.5,89.1 12.15,88.45 12.15,88.125
3V3 on Top Layer "NO TR" (solid, remove dead copper, pour order 178): 11.75,74.55 12.725,75.525 12.725,78.15 10.625,78.15 10.625,75.9 10.45,75.725 9.725,75.725 9.725,74.675 9.85,74.55
5V_VIN on Top Layer "NO TR" (solid, remove dead copper, pour order 176): 3.675,92.675 7.275,92.675 7.675,93.075 7.675,93.6 7.275,94 4.775,94 4.275,93.5 3.8,93.5 3.55,93.25 3.55,92.8
VDD_CORE on Top Layer "NO TR" (solid, remove dead copper, pour order 174): 17.5,89.95 17.5,91.564 18.063,92.127 18.748,92.127 19.05,91.825 19.05,89.925 18.9,89.775 17.675,89.775
VDD on Top Layer "NO TR" (solid, remove dead copper, pour order 172): 14.55,78.1 17.25,78.1 17.875,77.475 17.875,74.35 17.525,74 16.6,74 16.1,74.5 16.1,75.95 14.55,75.95
NetL4_1 on Top Layer "NO TR" (solid, remove dead copper, pour order 170): 11.325,81.575 11.35,81.6 11.55,81.6 11.575,81.575 11.575,81.3 12.725,80.153 12.725,79.225 12.675,79.175 10.675,79.175 10.625,79.225 10.625,79.975 11.325,80.675
5V_VIN on Top Layer "NO TR" (solid, remove dead copper, pour order 168): 10.925,81.575 10.95,81.6 11.15,81.6 11.175,81.575 11.175,80.725 10.5,80.05 10.5,78.475 7.95,78.475 7.775,78.65 7.775,79.025 7.9,79.15 8.825,79.15 9.175,79.5 9.438,79.75 9.701,79.75 9.75,79.801 9.75,80.338 10.925,81.451
5V_VIN on Top Layer "NO TR" (solid, remove dead copper, pour order 166): 14.425,78.575 14.325,78.475 13.075,78.475 13,78.55 13,80.075 12.525,80.55 12.525,81.575 12.55,81.6 12.75,81.6 12.775,81.575 12.775,81.293 14.425,79.656
NetL3_1 on Top Layer "NO TR" (solid, remove dead copper, pour order 164): 12.925,81.575 12.95,81.6 13.15,81.6 13.175,81.575 13.175,81.425 13.375,81.225 13.775,81.225 14.4,80.6 16.575,80.6 16.625,80.55 16.625,79.225 16.575,79.175 15.125,79.175 14.575,79.175 14.525,79.225 14.525,79.75 12.925,81.35
VDD_DDR on Top Layer "NO TR" (solid, pour order 160): 10.3,86.45 10.3,86.175 9.475,86.175 8.525,87.125 7.95,87.125 7.9,87.175 7.9,88.075 7.975,88.15 8.6,88.15
VTT_DDR on Top Layer "NO TR" (solid, remove dead copper, pour order 158): 9.7,85.775 7.875,85.775 7.7,85.95 7.7,86.7 7.875,86.875 8.65,86.875 9.075,86.45 9.55,85.975 9.7,85.975
NetL2_1 on Top Layer "NO TR" (solid, remove dead copper, pour order 156): 9.95,88.45 9.225,88.45 9.1,88.575 9.1,89.35 9.2,89.45 11.175,89.45 11.325,89.3 11.325,87.8 11.15,87.45 11.15,87.375 10.95,87.375 10.95,87.45
VDD_DDR on Top Layer "NO TR" (solid, remove dead copper, pour order 154): 11.3,91.3 10.85,91.75 8.2,91.75 7.975,91.525 7.975,90.125 8.075,90.025 9.525,90.025 10.8,90.025 11.3,90.525
NetL1_1 on Top Layer "NO TR" (solid, remove dead copper, pour order 114): 12.75,87.1 12.75,87.575 13.3,88.125 14.05,88.125 14.325,88.4 14.325,90.35 14.15,90.525 13.25,90.525 13.1,90.375 13.1,88.975 12.55,88.425 12.55,87.1
5V_VIN on Top Layer "NO TR" (solid, pour order 162): 8.675,89.05 7.588,89.05 6.475,89.95 6.475,90.15 5.7,90.15 5.7,88.425 5.85,88.275 8.6,88.275 10.35,86.525 10.75,86.525 10.75,87.45 9.875,88.325 9.35,88.325
GND on Bottom Layer "GND_L04_P184" (solid, remove dead copper, pour order 184): 89,64.25 66.25,64.25 66.25,67.9 63.75,67.9 63.75,66.75 52,66.75 52,78.25 51.5,78.75 38.75,78.75 37.75,77.75 37.75,68.625 35.575,66.45 27.7,66.45 27.5,66.25 27.5,58.5 28.25,57.75 35,57.75 35,52.75 36.5,51.25 36.5,46.25 37.5,45.25 52.45,45.25 52.9,45.7 52.9,49.9 53.2,50.2 63.25,50.175 64.5,50.175 64.5,55.3 63.25,55.3 63.25,60.75 66.25,60.75 66.25,64.25 86.5,64.25 89,64.25 89,0 0,0 0,99.25 0,99.5 0,120 89,120
VTT_DDR on Bottom Layer "VTT_DDR_BOT" (solid, remove dead copper, pour order 81): 63.975,51.095 63.975,54.925 62.775,54.925 62.775,61.345 65.705,61.345 65.705,67.595 64.205,67.595 64.205,66.345 58.95,66.345 58.705,66.345 54.205,66.345 51.425,66.345 51.425,65.095 54.725,65.095 59.45,65.095 61.65,65.095 63.955,65.095 63.955,62.345 61.4,62.345 61.4,52.345 50.955,52.345 50.955,51.095 55.705,51.095 55.705,50.595 57.455,50.595 57.455,51.095
GND on Signal Layer 1 "GND" (solid, remove dead copper, pour order 104): 0.408,119.592 89,119.592 89,0.408 0.408,0.408

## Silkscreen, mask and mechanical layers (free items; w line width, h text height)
Bottom Overlay:
  lines w0.15: 51.5,68 51.75,67.75 ; 51.5,70 60.75,70 ; 51.75,70 51.75,67.75 ; 52,68 51.75,67.75 ; 54.35,43.4 65.35,43.4 ; 62.75,48.6 62.75,49.3 ; 63.45,49.3 62.75,49.3 ; 64.55,43.4 64.55,47.3 62.75,49.3 ; 65.2,59.1 65,59.6 ; 65.4,59.9 65,59.6 ; 66.5,53 66.5,59.6 ; 66.5,59.2 65,59.6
